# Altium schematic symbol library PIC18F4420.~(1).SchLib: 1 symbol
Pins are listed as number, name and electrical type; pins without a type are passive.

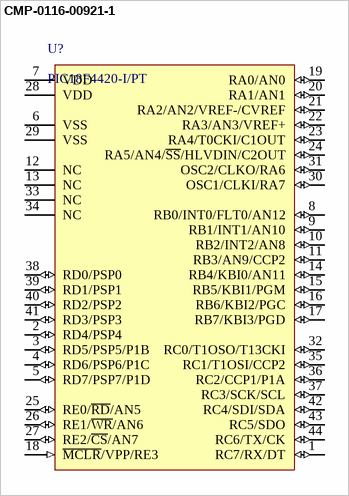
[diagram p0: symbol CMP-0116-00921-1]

## CMP-0116-00921-1
designator U?, comment PIC18F4420-I/PT
Enhanced Flash Microcontroller with 10-Bit A/D and nanoWatt Technology, 16K Flash, 44-Pin TQFP, Industrial Temperature Range
footprint TQFP-PT44_M (Thin QFP, 44-Leads, Body 10x10mm, Pitch 0.8mm, IPC Low Density)
footprint TQFP-PT44_N (Thin QFP, 44-Leads, Body 10x10mm, Pitch 0.8mm, IPC Medium Density)
footprint TQFP-PT44_L (Thin QFP, 44-Leads, Body 10x10mm, Pitch 0.8mm, IPC High Density)
pins: 1 RC7/RX/DT (io), 2 RD4/PSP4 (io), 3 RD5/PSP5/P1B (io), 4 RD6/PSP6/P1C (io), 5 RD7/PSP7/P1D (io), 6 VSS (power), 7 VDD (power), 8 RB0/INT0/FLT0/AN12 (io), 9 RB1/INT1/AN10 (io), 10 RB2/INT2/AN8 (io), 11 RB3/AN9/CCP2 (io), 12 NC, 13 NC, 14 RB4/KBI0/AN11 (io), 15 RB5/KBI1/PGM (io), 16 RB6/KBI2/PGC (io), 17 RB7/KBI3/PGD (io), 18 ~{MCLR}/VPP/RE3 (in), 19 RA0/AN0 (io), 20 RA1/AN1 (io), 21 RA2/AN2/VREF-/CVREF (io), 22 RA3/AN3/VREF+ (io), 23 RA4/T0CKI/C1OUT (io), 24 RA5/AN4/~{SS}/HLVDIN/C2OUT (io), 25 RE0/~{RD}/AN5 (io), 26 RE1/~{WR}/AN6 (io), 27 RE2/~{CS}/AN7 (io), 28 VDD (power), 29 VSS (power), 30 OSC1/CLKI/RA7 (io), 31 OSC2/CLKO/RA6 (io), 32 RC0/T1OSO/T13CKI (io), 33 NC, 34 NC, 35 RC1/T1OSI/CCP2 (io), 36 RC2/CCP1/P1A (io), 37 RC3/SCK/SCL (io), 38 RD0/PSP0 (io), 39 RD1/PSP1 (io), 40 RD2/PSP2 (io), 41 RD3/PSP3 (io), 42 RC4/SDI/SDA (io), 43 RC5/SDO (io), 44 RC6/TX/CK (io)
